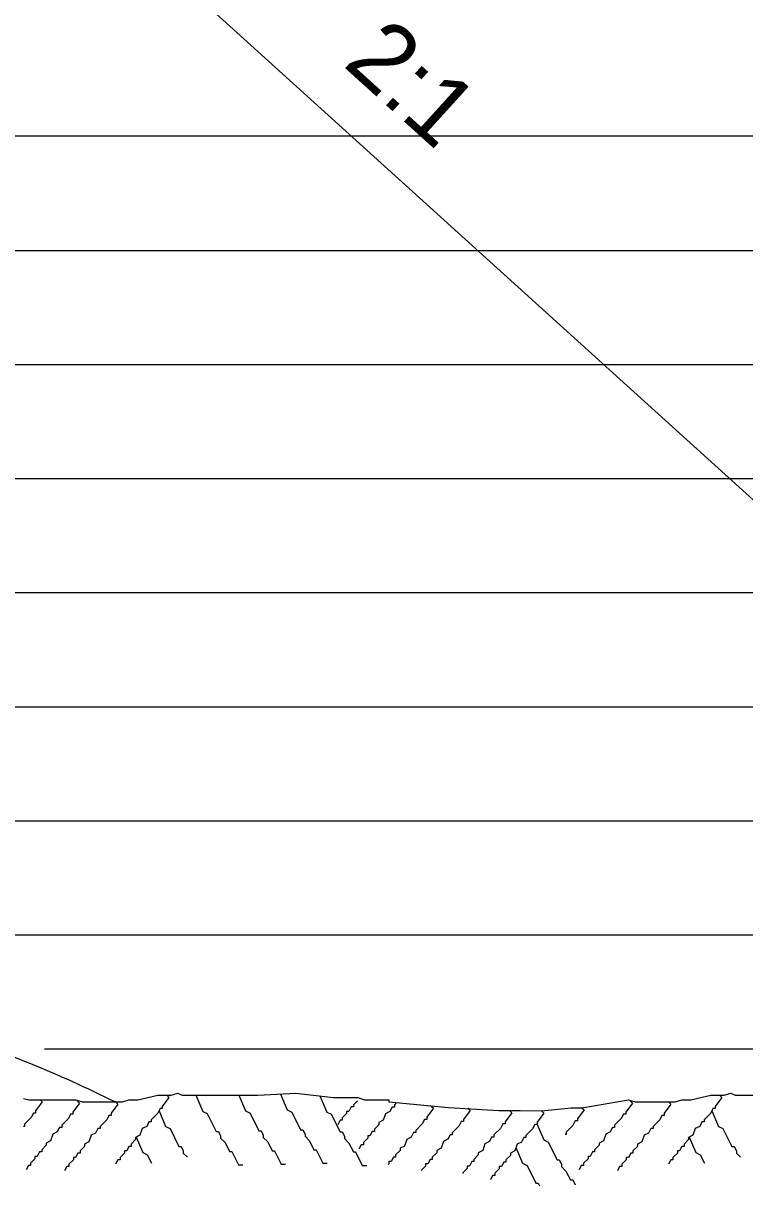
# Model space of a CAD drawing. Extents: x 49991.4 to 50021, y 49987.6 to 50011.4.
# Drawn here: x 50014.585 to 50015.211, y 50002.081 to 50003.09 of the extents above; entities that cross this region are included whole.
import ezdxf

# ---------------------------------------------------------------- set-up
doc = ezdxf.new("R2010")
doc.units = 0
doc.layers.add('Level 1', color=7, linetype='Continuous')
doc.layers.add('Level 2', color=7, linetype='Continuous')

msp = doc.modelspace()

# ---------------------------------------------------------------- linework, layer by layer
at = {"layer": 'Level 1'}
for p, q in [((50015.7875, 50002.1608), (50014.1088, 50003.6812)), ((50016.3368, 50002.9916), (50013.737, 50002.9916)), ((50013.737, 50002.8926), (50016.3368, 50002.8926)), ((50013.737, 50002.7936), (50016.3368, 50002.7936)), ((50014.133, 50002.6946), (50016.3368, 50002.6946)), ((50014.133, 50002.5956), (50016.3368, 50002.5956)), ((50014.133, 50002.4966), (50016.3368, 50002.4966)), ((50014.3288, 50002.3976), (50016.3368, 50002.3976)), ((50014.4666, 50002.2986), (50016.3368, 50002.2986)), ((50014.6037, 50002.1996), (50016.3368, 50002.1996))]:
    msp.add_line(p, q, dxfattribs=at)
for points in [[(50014.5854, 50002.1567), (50014.5902, 50002.1555), (50014.6308, 50002.1555), (50014.6365, 50002.1536), (50014.6713, 50002.1536), (50014.677, 50002.1555), (50014.6847, 50002.1555), (50014.7021, 50002.1594), (50014.7137, 50002.1594), (50014.7194, 50002.1613), (50014.7233, 50002.1594), (50014.7831, 50002.1594), (50014.7889, 50002.1594), (50014.8217, 50002.1613), (50014.8544, 50002.1575), (50014.8756, 50002.1575), (50014.8814, 50002.1555), (50014.8949, 50002.1555), (50014.9026, 50002.1555), (50014.9026, 50002.1536), (50014.9544, 50002.1489), (50014.9978, 50002.1463), (50015.0165, 50002.1461), (50015.0349, 50002.1458), (50015.0607, 50002.1484)], [(50014.5999, 50002.1555), (50014.6018, 50002.1536), (50014.596, 50002.1459), (50014.596, 50002.144), (50014.5941, 50002.144), (50014.5922, 50002.1401), (50014.5864, 50002.1344), (50014.5864, 50002.1324), (50014.5854, 50002.1324)], [(50014.6322, 50002.1546), (50014.6341, 50002.1527), (50014.6283, 50002.1449), (50014.6283, 50002.143), (50014.6264, 50002.143), (50014.6245, 50002.1392), (50014.6187, 50002.1334), (50014.6187, 50002.1314), (50014.6168, 50002.1314), (50014.6148, 50002.1276), (50014.611, 50002.1257), (50014.609, 50002.1199), (50014.6052, 50002.1179), (50014.6052, 50002.116), (50014.6013, 50002.1121), (50014.6013, 50002.1102), (50014.5994, 50002.1102), (50014.5975, 50002.1064), (50014.5955, 50002.1064), (50014.5955, 50002.1044), (50014.5917, 50002.1006), (50014.5917, 50002.0986), (50014.5898, 50002.0986), (50014.5878, 50002.0948)], [(50014.6654, 50002.1536), (50014.6673, 50002.1517), (50014.6616, 50002.144), (50014.6616, 50002.142), (50014.6597, 50002.142), (50014.6577, 50002.1382), (50014.652, 50002.1324), (50014.652, 50002.1305), (50014.65, 50002.1305), (50014.6481, 50002.1266), (50014.6442, 50002.1247), (50014.6423, 50002.1189), (50014.6384, 50002.117), (50014.6384, 50002.1151), (50014.6346, 50002.1112), (50014.6346, 50002.1093), (50014.6327, 50002.1093), (50014.6307, 50002.1054), (50014.6288, 50002.1054), (50014.6288, 50002.1035), (50014.6249, 50002.0996), (50014.6249, 50002.0977), (50014.623, 50002.0977), (50014.6211, 50002.0938)], [(50014.7098, 50002.1594), (50014.7117, 50002.1574), (50014.7059, 50002.1498), (50014.7059, 50002.1478), (50014.704, 50002.1478), (50014.7021, 50002.144), (50014.6963, 50002.1382), (50014.6963, 50002.1363), (50014.6943, 50002.1363), (50014.6924, 50002.1324), (50014.6886, 50002.1305), (50014.6866, 50002.1247), (50014.6828, 50002.1228), (50014.6828, 50002.1209), (50014.6789, 50002.117), (50014.6789, 50002.1151), (50014.677, 50002.1151), (50014.6751, 50002.1112), (50014.6732, 50002.1112), (50014.6732, 50002.1093), (50014.6693, 50002.1054), (50014.6693, 50002.1035), (50014.6673, 50002.1035), (50014.6654, 50002.0996)], [(50014.7353, 50002.1589), (50014.7411, 50002.1454), (50014.7449, 50002.1435), (50014.7527, 50002.128), (50014.7546, 50002.128), (50014.7565, 50002.1242), (50014.7565, 50002.1223), (50014.7604, 50002.1184), (50014.7642, 50002.1107), (50014.7662, 50002.1107), (50014.772, 50002.0991), (50014.7758, 50002.0991)], [(50014.7724, 50002.1594), (50014.7782, 50002.1459), (50014.7821, 50002.144), (50014.7898, 50002.1285), (50014.7917, 50002.1285), (50014.7936, 50002.1247), (50014.7936, 50002.1228), (50014.7975, 50002.1189), (50014.8014, 50002.1112), (50014.8033, 50002.1112), (50014.8091, 50002.0996), (50014.8129, 50002.0996)], [(50014.8086, 50002.1603), (50014.8143, 50002.1469), (50014.8182, 50002.1449), (50014.8259, 50002.1295), (50014.8279, 50002.1295), (50014.8298, 50002.1257), (50014.8298, 50002.1238), (50014.8337, 50002.1199), (50014.8375, 50002.1121), (50014.8395, 50002.1121), (50014.8452, 50002.1006), (50014.8491, 50002.1006)], [(50014.8428, 50002.1584), (50014.8486, 50002.1449), (50014.8525, 50002.143), (50014.8602, 50002.1276), (50014.8621, 50002.1276), (50014.864, 50002.1238), (50014.864, 50002.1218), (50014.8679, 50002.1179), (50014.8717, 50002.1102), (50014.8736, 50002.1102), (50014.8794, 50002.0986), (50014.8833, 50002.0986)], [(50014.8752, 50002.1547), (50014.8717, 50002.1512), (50014.8717, 50002.1493), (50014.8698, 50002.1493), (50014.8679, 50002.1454), (50014.8659, 50002.1454), (50014.8659, 50002.1435), (50014.862, 50002.1397), (50014.862, 50002.1377), (50014.8602, 50002.1377), (50014.8582, 50002.1339)], [(50014.9089, 50002.1528), (50014.9074, 50002.1512), (50014.9074, 50002.1492), (50014.9054, 50002.1492), (50014.9035, 50002.1454), (50014.8997, 50002.1434), (50014.8977, 50002.1377), (50014.8939, 50002.1357), (50014.8939, 50002.1338), (50014.89, 50002.1299), (50014.89, 50002.128), (50014.8881, 50002.128), (50014.8861, 50002.1242), (50014.8842, 50002.1242), (50014.8842, 50002.1222), (50014.8804, 50002.1184), (50014.8804, 50002.1165), (50014.8784, 50002.1165), (50014.8765, 50002.1126)], [(50015.0607, 50002.1484), (50015.07, 50002.1486), (50015.1105, 50002.1555), (50015.1163, 50002.1536), (50015.151, 50002.1536), (50015.1568, 50002.1555), (50015.1645, 50002.1555), (50015.1818, 50002.1594), (50015.1934, 50002.1594), (50015.1991, 50002.1613), (50015.203, 50002.1594), (50015.2628, 50002.1594)], [(50015.1119, 50002.1546), (50015.1138, 50002.1527), (50015.108, 50002.1449), (50015.108, 50002.143), (50015.1062, 50002.143), (50015.1042, 50002.1392), (50015.0984, 50002.1334), (50015.0984, 50002.1314), (50015.0965, 50002.1314), (50015.0946, 50002.1276), (50015.0907, 50002.1257), (50015.0888, 50002.1199), (50015.0849, 50002.1179), (50015.0849, 50002.116), (50015.081, 50002.1121), (50015.081, 50002.1102), (50015.0791, 50002.1102), (50015.0772, 50002.1064), (50015.0753, 50002.1064), (50015.0753, 50002.1044), (50015.0714, 50002.1006), (50015.0714, 50002.0986), (50015.0695, 50002.0986), (50015.0675, 50002.0948)], [(50015.1452, 50002.1536), (50015.1471, 50002.1517), (50015.1413, 50002.144), (50015.1413, 50002.142), (50015.1394, 50002.142), (50015.1375, 50002.1382), (50015.1317, 50002.1324), (50015.1317, 50002.1305), (50015.1297, 50002.1305), (50015.1278, 50002.1266), (50015.124, 50002.1247), (50015.122, 50002.1189), (50015.1182, 50002.117), (50015.1182, 50002.1151), (50015.1143, 50002.1112), (50015.1143, 50002.1093), (50015.1124, 50002.1093), (50015.1105, 50002.1054), (50015.1085, 50002.1054), (50015.1085, 50002.1035), (50015.1047, 50002.0996), (50015.1047, 50002.0977), (50015.1027, 50002.0977), (50015.1008, 50002.0938)], [(50015.1895, 50002.1594), (50015.1914, 50002.1574), (50015.1857, 50002.1498), (50015.1857, 50002.1478), (50015.1837, 50002.1478), (50015.1818, 50002.144), (50015.176, 50002.1382), (50015.176, 50002.1363), (50015.1741, 50002.1363), (50015.1722, 50002.1324), (50015.1683, 50002.1305), (50015.1663, 50002.1247), (50015.1625, 50002.1228), (50015.1625, 50002.1209), (50015.1586, 50002.117), (50015.1586, 50002.1151), (50015.1567, 50002.1151), (50015.1548, 50002.1112), (50015.1529, 50002.1112), (50015.1529, 50002.1093), (50015.149, 50002.1054), (50015.149, 50002.1035), (50015.1471, 50002.1035), (50015.1452, 50002.0996)], [(50014.7031, 50002.1459), (50014.7088, 50002.1324), (50014.7127, 50002.1305), (50014.7204, 50002.1151), (50014.7223, 50002.1151), (50014.7242, 50002.1112), (50014.7242, 50002.1093), (50014.7278, 50002.1057)], [(50014.9392, 50002.1501), (50014.9412, 50002.1482), (50014.9354, 50002.1404), (50014.9354, 50002.1385), (50014.9334, 50002.1385), (50014.9315, 50002.1346), (50014.9258, 50002.1289), (50014.9258, 50002.127), (50014.9238, 50002.127), (50014.9219, 50002.1231), (50014.918, 50002.1211), (50014.9161, 50002.1154), (50014.9122, 50002.1134), (50014.9122, 50002.1115), (50014.9084, 50002.1077), (50014.9084, 50002.1058), (50014.9065, 50002.1058), (50014.9045, 50002.1019), (50014.9026, 50002.1019), (50014.9026, 50002.0999), (50014.902, 50002.0993)], [(50014.971, 50002.1481), (50014.973, 50002.1462), (50014.9672, 50002.1385), (50014.9672, 50002.1366), (50014.9653, 50002.1366), (50014.9633, 50002.1327), (50014.9575, 50002.1269), (50014.9575, 50002.125), (50014.9556, 50002.125), (50014.9537, 50002.1212), (50014.9498, 50002.1192), (50014.9479, 50002.1134), (50014.944, 50002.1115), (50014.944, 50002.1096), (50014.9402, 50002.1057), (50014.9402, 50002.1038), (50014.9383, 50002.1038), (50014.9363, 50002.0999), (50014.9344, 50002.0999), (50014.9344, 50002.098), (50014.9305, 50002.0941)], [(50015.0071, 50002.1462), (50015.0091, 50002.1443), (50015.0033, 50002.1365), (50015.0033, 50002.1346), (50015.0013, 50002.1346), (50014.9994, 50002.1307), (50014.9937, 50002.125), (50014.9937, 50002.123), (50014.9917, 50002.123), (50014.9898, 50002.1192), (50014.9859, 50002.1173), (50014.984, 50002.1115), (50014.9801, 50002.1096), (50014.9801, 50002.1076), (50014.9763, 50002.1038), (50014.9763, 50002.1019), (50014.9744, 50002.1019), (50014.9724, 50002.098), (50014.9705, 50002.098), (50014.9705, 50002.096), (50014.9666, 50002.0922), (50014.9666, 50002.0915)], [(50015.0349, 50002.1458), (50015.0369, 50002.1439), (50015.0311, 50002.1361), (50015.0311, 50002.1342), (50015.0291, 50002.1342), (50015.0272, 50002.1303), (50015.0214, 50002.1246), (50015.0214, 50002.1227), (50015.0195, 50002.1227), (50015.0176, 50002.1188), (50015.0137, 50002.1169), (50015.0118, 50002.1111), (50015.008, 50002.1092), (50015.008, 50002.1072), (50015.0041, 50002.1034), (50015.0041, 50002.1014), (50015.0022, 50002.1014), (50015.0002, 50002.0976), (50014.9983, 50002.0976), (50014.9983, 50002.0956), (50014.9945, 50002.0918), (50014.9945, 50002.0899), (50014.9925, 50002.0899), (50014.9906, 50002.086)], [(50015.07, 50002.1486), (50015.0719, 50002.1467), (50015.0661, 50002.139), (50015.0661, 50002.1371), (50015.0642, 50002.1371), (50015.0622, 50002.1332), (50015.0564, 50002.1275), (50015.0564, 50002.1255), (50015.0555, 50002.1255)], [(50015.1828, 50002.1459), (50015.1885, 50002.1324), (50015.1924, 50002.1305), (50015.2001, 50002.1151), (50015.202, 50002.1151), (50015.204, 50002.1112), (50015.204, 50002.1093), (50015.2075, 50002.1057)], [(50015.0311, 50002.1342), (50015.0369, 50002.1207), (50015.0408, 50002.1188), (50015.0485, 50002.1033), (50015.0504, 50002.1033), (50015.0524, 50002.0995), (50015.0524, 50002.0976), (50015.0562, 50002.0937), (50015.06, 50002.086), (50015.062, 50002.086), (50015.0642, 50002.0816)], [(50014.6833, 50002.1232), (50014.6891, 50002.1097), (50014.6929, 50002.1078), (50014.6966, 50002.1004)], [(50015.163, 50002.1232), (50015.1688, 50002.1097), (50015.1726, 50002.1078), (50015.1763, 50002.1004)], [(50015.0128, 50002.114), (50015.0185, 50002.1005), (50015.0224, 50002.0985), (50015.0301, 50002.0831), (50015.0321, 50002.0831), (50015.0332, 50002.0809)]]:
    msp.add_lwpolyline(points, dxfattribs=at)
msp.add_spline([(50014.0999, 50002.3633), (50014.1267, 50002.3991), (50014.1854, 50002.4192), (50014.2789, 50002.4005), (50014.3483, 50002.3738), (50014.395, 50002.319), (50014.4698, 50002.271), (50014.5285, 50002.2162), (50014.5886, 50002.1882), (50014.6655, 50002.1536)], degree=3, dxfattribs=at)

# ---------------------------------------------------------------- texts
at = {"layer": 'Level 2'}
msp.add_text('2:1', height=0.06, rotation=317.8325, dxfattribs=at).set_placement((50014.8616, 50003.0534))

doc.saveas('drawing.dxf')
